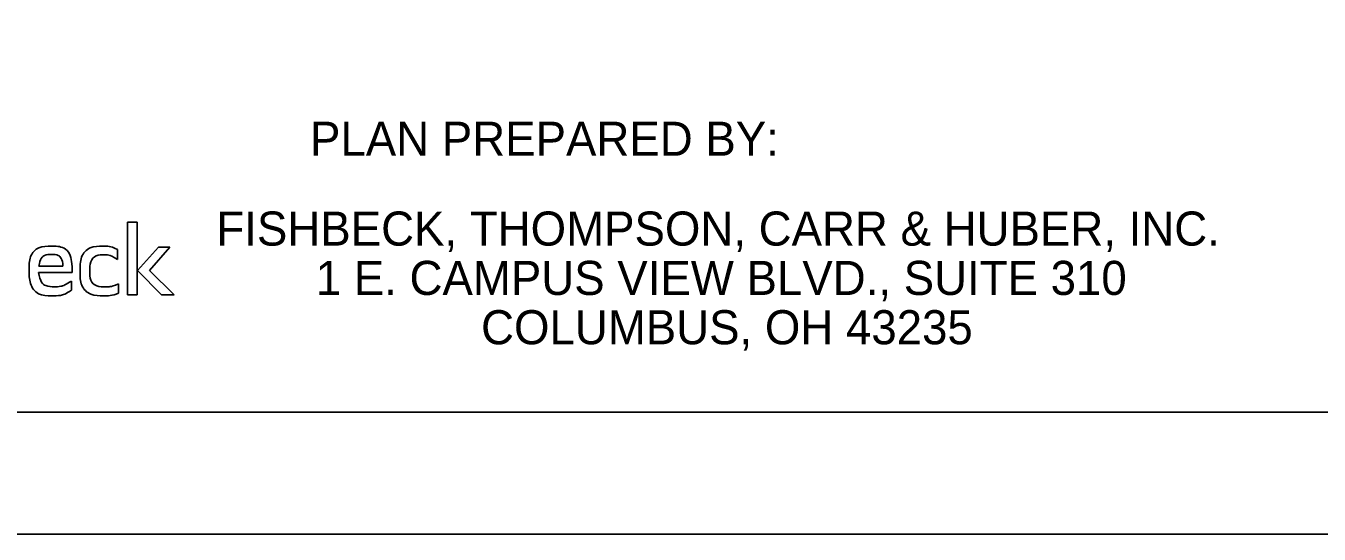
# Model space of a CAD drawing. Extents: x 0 to 34, y 0 to 22.
# Drawn here: x 2.94 to 8.25, y 0 to 2.09 of the extents above; entities that cross this region are included whole.
import ezdxf

# ---------------------------------------------------------------- set-up
doc = ezdxf.new("R2010")
doc.units = 0
for name, color, linetype in [('SH_Border', 7, 'Continuous'), ('SH_Cut_Line', 7, 'Continuous'), ('SH_Data', 7, 'Continuous'), ('SH_Text', 7, 'Continuous')]:
    doc.layers.add(name, color=color, linetype=linetype)

msp = doc.modelspace()

# ---------------------------------------------------------------- linework, layer by layer
at = {"layer": 'SH_Border'}
msp.add_lwpolyline([(1.5, 21.5), (33.5, 21.5), (33.5, 0.5), (1.5, 0.5)], close=True, dxfattribs=at)
at = {"layer": 'SH_Cut_Line'}
msp.add_lwpolyline([(0, 0), (34, 0), (34, 22), (0, 22)], close=True, dxfattribs=at)
at = {"layer": 'SH_Data'}
for p, q in [((3.3951, 1.28), (3.3562, 1.28)), ((3.3562, 1.28), (3.3562, 0.9821)), ((3.3951, 0.9821), (3.3951, 1.28)), ((3.3154, 1.1271), (3.3154, 1.1686)), ((3.4838, 1.1782), (3.3968, 1.0821)), ((3.4462, 1.0821), (3.5301, 1.1782)), ((3.5301, 1.1782), (3.4838, 1.1782)), ((2.9912, 1.0743), (3.1292, 1.0743)), ((3.0908, 1.1001), (2.992, 1.1001)), ((3.3968, 1.0821), (3.4951, 0.9821)), ((3.5476, 0.9821), (3.4462, 1.0821)), ((3.1257, 1.0013), (3.1257, 1.0389)), ((3.3198, 0.9895), (3.3198, 1.028)), ((3.3562, 0.9821), (3.3951, 0.9821)), ((3.4951, 0.9821), (3.5476, 0.9821))]:
    msp.add_line(p, q, dxfattribs=at)
for points in [[(3.1292, 1.0743), (3.1292, 1.1468), (3.096, 1.1822), (3.044, 1.1822), (2.9899, 1.1822), (2.9523, 1.142), (2.9523, 1.0826), (2.9523, 1.0284), (2.9864, 0.9782), (3.0475, 0.9782), (3.0807, 0.9782), (3.1021, 0.9856), (3.1257, 1.0013)], [(3.3154, 1.1686), (3.2966, 1.1769), (3.2813, 1.1822), (3.2586, 1.1822), (3.1992, 1.1822), (3.1616, 1.1411), (3.1616, 1.0765), (3.1616, 1.0188), (3.2027, 0.9782), (3.2612, 0.9782), (3.2818, 0.9782), (3.3067, 0.9834), (3.3198, 0.9895)], [(2.992, 1.1001), (2.9973, 1.1311), (3.0152, 1.1485), (3.0449, 1.1485), (3.0724, 1.1485), (3.0895, 1.1298), (3.0908, 1.1001)], [(3.3198, 1.028), (3.3001, 1.0192), (3.2844, 1.0149), (3.2678, 1.0149), (3.2276, 1.0149), (3.2014, 1.0393), (3.2014, 1.08), (3.2014, 1.1197), (3.2259, 1.1464), (3.2612, 1.1464), (3.2783, 1.1464), (3.2931, 1.142), (3.3154, 1.1271)], [(3.1257, 1.0389), (3.103, 1.024), (3.0807, 1.0153), (3.0571, 1.0153), (3.0196, 1.0153), (2.9973, 1.0354), (2.9912, 1.0743)]]:
    msp.add_open_spline(points, degree=3, dxfattribs=at)

# ---------------------------------------------------------------- texts
at = {"layer": 'SH_Text'}
for s, p in [('PLAN PREPARED BY:', (4.1053, 1.553)), ('FISHBECK, THOMPSON, CARR & HUBER, INC.', (3.7211, 1.1843)), ('1 E. CAMPUS VIEW BLVD., SUITE 310', (4.1288, 0.9818)), ('COLUMBUS, OH 43235', (4.8075, 0.7793))]:
    msp.add_text(s, height=0.14, dxfattribs=at).set_placement(p)

doc.saveas('drawing.dxf')
